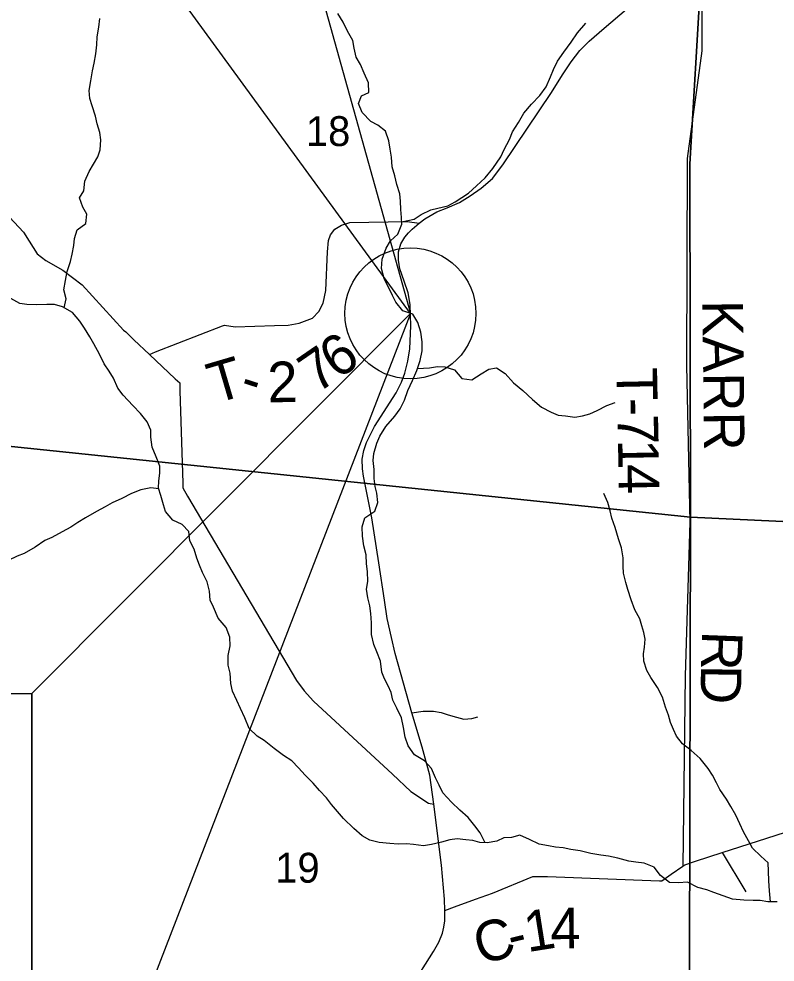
# Model space of a CAD drawing. Extents: x 0 to 34, y 0 to 22.
# Drawn here: x 26.174 to 27.233, y 16.193 to 17.514 of the extents above; entities that cross this region are included whole.
import ezdxf

# ---------------------------------------------------------------- set-up
doc = ezdxf.new("R2010")
doc.units = 0
for name, color, linetype in [('GM_X_Corporation', 7, 'Continuous'), ('GM_X_County_Road', 7, 'Continuous'), ('GM_X_County_Road_Text', 7, 'Continuous'), ('GM_X_Minor_River', 7, 'Continuous'), ('GM_X_Section_Text', 7, 'Continuous'), ('GM_X_State_Route', 7, 'Continuous'), ('GM_X_Township_Road', 7, 'Continuous'), ('GM_X_Township_Road_Text', 7, 'Continuous'), ('SH_Data', 7, 'Continuous')]:
    doc.layers.add(name, color=color, linetype=linetype)

msp = doc.modelspace()

# ---------------------------------------------------------------- linework, layer by layer
at = {"layer": 'GM_X_Corporation'}
for points in [[(26.3421, 17.8905), (26.9688, 17.8482), (27.1442, 17.8319), (27.1132, 17.3107), (27.1145, 16.8163), (26.06, 16.9257), (26.0658, 16.9791), (26.1183, 17.6235)], [(26.0314, 16.5691), (26.06, 16.9257), (27.1145, 16.8163), (27.112, 15.7689), (26.1924, 15.8415)]]:
    msp.add_lwpolyline(points, dxfattribs=at)
for points in [[(27.1442, 17.8319), (27.2101, 17.8272), (28.2146, 17.7472), (28.2741, 17.7417), (28.199, 16.7653), (27.1145, 16.8163), (27.1132, 17.3107)], [(27.1145, 16.8163), (28.199, 16.7653), (28.1104, 15.671), (27.112, 15.7689)]]:
    msp.add_lwpolyline(points, close=True, dxfattribs=at)
at = {"layer": 'GM_X_County_Road'}
msp.add_lwpolyline([(26.7705, 16.2651), (26.7841, 16.2703), (26.8132, 16.281), (26.8372, 16.2896), (26.8937, 16.313), (26.9141, 16.3129), (27.0708, 16.3069), (27.0742, 16.3068), (27.0874, 16.3161), (27.1034, 16.3274), (27.1064, 16.3295), (27.1215, 16.3344), (27.1588, 16.3464), (27.448, 16.4395), (27.452, 16.4408), (27.4615, 16.4528), (27.5592, 16.5754), (27.5725, 16.5898), (27.6861, 16.7116), (27.6929, 16.7189)], dxfattribs=at)
at = {"layer": 'GM_X_Minor_River'}
for points in [[(26.827, 16.3603), (26.82, 16.3743), (26.8125, 16.3838), (26.8031, 16.3956), (26.7914, 16.4059), (26.7797, 16.4169), (26.7676, 16.4302), (26.7624, 16.4408), (26.7571, 16.4511), (26.7519, 16.464), (26.7417, 16.475), (26.7281, 16.4834), (26.7191, 16.496), (26.715, 16.5081), (26.7127, 16.5218), (26.7098, 16.5351), (26.7034, 16.5487), (26.6978, 16.5597), (26.6951, 16.5704), (26.691, 16.5802), (26.6861, 16.5897), (26.6824, 16.5992), (26.6802, 16.6144), (26.6753, 16.6277), (26.6712, 16.6379), (26.6678, 16.652), (26.6679, 16.6683), (26.6668, 16.6815), (26.6653, 16.6922), (26.6627, 16.7032), (26.6609, 16.7153), (26.6624, 16.7259), (26.6621, 16.7399), (26.6606, 16.7506), (26.6603, 16.7634), (26.6569, 16.776), (26.6551, 16.7896), (26.6548, 16.8025), (26.6586, 16.8154), (26.6726, 16.8244), (26.6765, 16.8365), (26.6754, 16.8498), (26.6728, 16.8593), (26.6713, 16.8703), (26.6713, 16.8828), (26.6702, 16.8957), (26.671, 16.9052), (26.6753, 16.9199), (26.6795, 16.9298), (26.6878, 16.943), (26.7004, 16.9574), (26.708, 16.968), (26.7137, 16.9801), (26.7187, 16.9937), (26.7251, 17.0077), (26.7312, 17.0217), (26.7358, 17.0357), (26.7385, 17.049), (26.7386, 17.0615), (26.7367, 17.0751), (26.7326, 17.0888), (26.7255, 17.1006), (26.7115, 17.1052), (26.7017, 17.1173), (26.6972, 17.1268), (26.6856, 17.1504), (26.6815, 17.1644), (26.6826, 17.1773), (26.6884, 17.1928), (26.6945, 17.2034), (26.7047, 17.2125), (26.7101, 17.2265), (26.7097, 17.236), (26.709, 17.247), (26.7083, 17.2587), (26.7072, 17.269), (26.7031, 17.2819), (26.7005, 17.2944), (26.6967, 17.3069), (26.6956, 17.3202), (26.6938, 17.3316), (26.692, 17.3433), (26.6871, 17.3566), (26.6765, 17.365), (26.6667, 17.3703), (26.6546, 17.3829), (26.6494, 17.3954), (26.6536, 17.4064), (26.6642, 17.4109), (26.6635, 17.4245), (26.6575, 17.4378), (26.6522, 17.45), (26.6462, 17.4602), (26.6433, 17.4731), (26.6414, 17.4838), (26.6339, 17.4967), (26.6279, 17.5092), (26.6207, 17.5217)], [(26.2374, 17.1095), (26.2402, 17.1218), (26.2368, 17.1347), (26.2392, 17.1475), (26.2419, 17.16), (26.2464, 17.1744), (26.2488, 17.1843), (26.2511, 17.1968), (26.2519, 17.2066), (26.2557, 17.2184), (26.2678, 17.2274), (26.2694, 17.2403), (26.2637, 17.2502), (26.2589, 17.2635), (26.265, 17.2733), (26.2662, 17.2866), (26.2723, 17.3002), (26.2844, 17.3206), (26.2879, 17.3308), (26.2887, 17.3445), (26.2876, 17.3547), (26.2835, 17.3668), (26.2812, 17.3779), (26.2768, 17.3923), (26.2734, 17.4025), (26.2727, 17.4135), (26.275, 17.4272), (26.2773, 17.4412), (26.2796, 17.4518), (26.2819, 17.465), (26.2831, 17.4775), (26.2839, 17.4889), (26.2862, 17.5025), (26.2874, 17.5147)], [(26.7099, 17.2298), (26.7275, 17.2336), (26.7373, 17.24), (26.751, 17.2464), (26.7608, 17.249), (26.7745, 17.2524), (26.7847, 17.258), (26.7942, 17.2637), (26.8037, 17.2701), (26.8147, 17.2803), (26.8268, 17.2912), (26.8378, 17.3045), (26.8489, 17.3207), (26.8534, 17.3309), (26.8607, 17.3453), (26.8653, 17.3559), (26.8733, 17.3688), (26.8812, 17.382), (26.8915, 17.3945), (26.9033, 17.4069), (26.9124, 17.419), (26.9181, 17.433), (26.9227, 17.4429), (26.928, 17.455), (26.9372, 17.4675), (26.9474, 17.4814), (26.9562, 17.4943), (26.968, 17.5079)], [(26.4268, 16.7488), (26.4231, 16.7587), (26.4193, 16.7712), (26.4133, 16.783), (26.4119, 16.7959), (26.4025, 16.8058), (26.3896, 16.8119), (26.3791, 16.824), (26.3765, 16.8335), (26.3727, 16.8464), (26.3697, 16.857), (26.3701, 16.8669), (26.3713, 16.8779), (26.3714, 16.8874), (26.3665, 16.9007), (26.3605, 16.9143), (26.359, 16.9284), (26.3587, 16.9378), (26.3538, 16.9496), (26.3444, 16.9614), (26.3335, 16.9724), (26.3199, 16.9869), (26.3127, 16.9968), (26.3067, 17.0108), (26.3004, 17.0207), (26.2936, 17.031), (26.2868, 17.0446), (26.2789, 17.0591), (26.2733, 17.0689), (26.2658, 17.0811), (26.2594, 17.0906), (26.2492, 17.1028), (26.2352, 17.1108), (26.2239, 17.1142), (26.2133, 17.1139), (26.1982, 17.1136), (26.1853, 17.114), (26.1755, 17.1152), (26.163, 17.1224)], [(26.7322, 17.0246), (26.7487, 17.0254), (26.76, 17.0273), (26.7702, 17.0269), (26.7838, 17.0226), (26.7944, 17.0105), (26.8084, 17.0085), (26.8213, 17.0168), (26.8319, 17.0236), (26.8425, 17.0251), (26.8549, 17.0174), (26.8666, 17.0045), (26.8798, 16.9935), (26.893, 16.9809), (26.9058, 16.9702), (26.9194, 16.963), (26.9292, 16.9592), (26.9391, 16.958), (26.9523, 16.9564), (26.9633, 16.9579), (26.9735, 16.9609), (26.9837, 16.9654), (26.997, 16.9725), (27.0087, 16.9767)], [(26.37, 16.856), (26.3588, 16.8571), (26.3448, 16.8545), (26.3319, 16.8492), (26.3182, 16.8425), (26.3046, 16.8361), (26.2947, 16.8308), (26.2826, 16.824), (26.2674, 16.8154), (26.2568, 16.8086), (26.247, 16.8022), (26.2345, 16.7958), (26.2204, 16.7879), (26.2102, 16.7837), (26.1969, 16.7743), (26.1814, 16.7653), (26.1719, 16.7615), (26.159, 16.7555), (26.148, 16.7533), (26.1234, 16.7477), (26.1132, 16.7466), (26.1019, 16.747)], [(27.2263, 16.2776), (27.2249, 16.2928), (27.2238, 16.3068), (27.2235, 16.3204), (27.2228, 16.3322), (27.2126, 16.3413), (27.2013, 16.3527), (27.1953, 16.363), (27.1885, 16.3755), (27.1832, 16.3869), (27.1776, 16.3987), (27.1708, 16.4112), (27.1645, 16.4211), (27.1554, 16.4348), (27.1505, 16.4443), (27.1453, 16.4549), (27.1389, 16.4644), (27.128, 16.4781), (27.1151, 16.4895), (27.1031, 16.4987), (27.0948, 16.5093), (27.0903, 16.5188), (27.0865, 16.5287), (27.0835, 16.5389), (27.0794, 16.5503), (27.0753, 16.564), (27.0682, 16.5777), (27.0588, 16.5917), (27.0531, 16.6016), (27.049, 16.6145), (27.0483, 16.6247), (27.0499, 16.6342), (27.051, 16.6452), (27.0492, 16.6547), (27.0462, 16.6642), (27.0436, 16.674), (27.0364, 16.6862), (27.0312, 16.7002), (27.0267, 16.7147), (27.0237, 16.7249), (27.0204, 16.7378), (27.02, 16.7477), (27.0201, 16.7594), (27.0175, 16.7731), (27.0133, 16.786), (27.0089, 16.8019), (27.004, 16.8148), (27.0018, 16.8251), (26.9988, 16.8365), (26.9931, 16.8494)], [(27.2358, 16.2776), (27.2226, 16.2776), (27.2116, 16.2792), (27.2018, 16.2792), (27.1889, 16.2796), (27.173, 16.2812), (27.1598, 16.2858), (27.1469, 16.2904), (27.1371, 16.2942), (27.1246, 16.2977), (27.1103, 16.3049), (27.0974, 16.3042), (27.085, 16.3047), (27.0725, 16.3142), (27.0635, 16.326), (27.0495, 16.3317), (27.0378, 16.3329), (27.0279, 16.3345), (27.0128, 16.3387), (26.9996, 16.3414), (26.989, 16.3426), (26.9746, 16.3453), (26.9599, 16.3491), (26.947, 16.3507), (26.9361, 16.353), (26.9255, 16.3542), (26.9153, 16.3557), (26.9024, 16.3584), (26.8888, 16.3649), (26.8752, 16.3707), (26.8639, 16.3677), (26.8529, 16.367), (26.8431, 16.3625), (26.8298, 16.3602), (26.8196, 16.3606), (26.8098, 16.3633), (26.7996, 16.3645), (26.7878, 16.3657), (26.7776, 16.3642), (26.7655, 16.3609), (26.7515, 16.3579), (26.7405, 16.356), (26.7265, 16.3576), (26.7167, 16.3588), (26.705, 16.3584), (26.6936, 16.3592), (26.6785, 16.3604), (26.6653, 16.3639), (26.6547, 16.37), (26.643, 16.3803), (26.6287, 16.394), (26.62, 16.4042), (26.6117, 16.4138), (26.6046, 16.4233), (26.5948, 16.4335), (26.5861, 16.4438), (26.5748, 16.4548), (26.5654, 16.4651), (26.556, 16.475), (26.5443, 16.4822), (26.5314, 16.4921), (26.5175, 16.5032), (26.5077, 16.5093), (26.4964, 16.5203), (26.4904, 16.5351), (26.4844, 16.5484), (26.4791, 16.5594), (26.4731, 16.5727), (26.4709, 16.5834), (26.4698, 16.5978), (26.4672, 16.6091), (26.4672, 16.6224), (26.4699, 16.6361), (26.4692, 16.6482), (26.4643, 16.6618), (26.453, 16.6748), (26.4463, 16.69), (26.4418, 16.6998), (26.4407, 16.7127), (26.4377, 16.7256), (26.431, 16.7389), (26.4268, 16.7488)]]:
    msp.add_lwpolyline(points, dxfattribs=at)
at = {"layer": 'GM_X_State_Route'}
msp.add_lwpolyline([(26.692, 16.109), (26.7547, 16.208), (26.7622, 16.2211), (26.7672, 16.2337), (26.7692, 16.2418), (26.7704, 16.2509), (26.7705, 16.2651), (26.7697, 16.2812), (26.7657, 16.329), (26.755, 16.4142), (26.7494, 16.4549), (26.7385, 16.4939), (26.7243, 16.5421), (26.7007, 16.6252), (26.6957, 16.6475), (26.6896, 16.6741), (26.686, 16.6998), (26.6781, 16.7524), (26.6684, 16.8152), (26.6566, 16.8737), (26.6551, 16.8837), (26.6547, 16.8975), (26.6569, 16.9094), (26.6607, 16.9206), (26.6643, 16.9283), (26.6717, 16.9431), (26.7023, 16.9904), (26.7097, 17.0052), (26.7143, 17.0179), (26.7185, 17.0347), (26.7213, 17.0518), (26.723, 17.084), (26.7218, 17.1139), (26.7189, 17.1303), (26.7136, 17.1468), (26.7075, 17.1639), (26.7055, 17.1762), (26.7057, 17.1876), (26.709, 17.1991), (26.7146, 17.2081), (26.7195, 17.2145), (26.7246, 17.2193), (26.7343, 17.228), (26.7422, 17.2339), (26.7593, 17.2438), (26.7735, 17.2495), (26.7908, 17.2568), (26.8059, 17.266), (26.8212, 17.2768), (26.8373, 17.2903), (26.8518, 17.3097), (26.9195, 17.4111), (26.9351, 17.4355), (26.9473, 17.4539), (26.9593, 17.4695), (26.9725, 17.483), (26.9933, 17.5012), (27.0652, 17.5627)], dxfattribs=at)
at = {"layer": 'GM_X_Township_Road'}
msp.add_line((27.1588, 16.3464), (27.1918, 16.2915), dxfattribs=at)
for points in [[(27.1295, 17.6076), (27.1302, 17.4692), (27.1094, 17.3183), (27.1089, 17.0285), (27.1135, 16.8092), (27.107, 16.5939), (27.1034, 16.3274)], [(26.1609, 17.2361), (26.1805, 17.2153), (26.1884, 17.2028), (26.1995, 17.185), (26.2119, 17.1757), (26.2358, 17.162), (26.2629, 17.1416), (26.3205, 17.0781), (26.3238, 17.0756), (26.3352, 17.0647), (26.3569, 17.0442), (26.393, 17.0101), (26.3993, 17.0042), (26.3996, 16.9929), (26.4037, 16.8637), (26.4038, 16.8572), (26.4102, 16.8454), (26.5628, 16.5873), (26.5734, 16.573), (26.5867, 16.5584), (26.697, 16.4561), (26.723, 16.432), (26.7473, 16.4155), (26.755, 16.4142)], [(26.3569, 17.0442), (26.3654, 17.0476), (26.4591, 17.084), (26.4619, 17.0851), (26.477, 17.0827), (26.5321, 17.0846), (26.551, 17.0851), (26.5666, 17.0878), (26.5849, 17.0948), (26.5942, 17.1042), (26.6, 17.116), (26.6038, 17.1338), (26.6061, 17.188), (26.6074, 17.2038), (26.6102, 17.2117), (26.6164, 17.2193), (26.6256, 17.2252), (26.6376, 17.2288), (26.7175, 17.2301), (26.7343, 17.228)], [(26.7243, 16.5421), (26.7399, 16.5444), (26.7545, 16.5447), (26.7652, 16.5424), (26.7749, 16.5395), (26.7866, 16.536), (26.797, 16.5334), (26.8083, 16.5344), (26.8167, 16.5367)]]:
    msp.add_lwpolyline(points, dxfattribs=at)
at = {"layer": 'SH_Data'}
for points in [[(26.3421, 18.4635), (26.7223, 17.1016), (26.3421, 17.6235)], [(26.1924, 16.5691), (26.7223, 17.1016), (26.1924, 15.7291)], [(24.3169, 16.5691), (26.1924, 16.5691), (26.1924, 15.7291), (24.3169, 15.7291)]]:
    msp.add_lwpolyline(points, close=True, dxfattribs=at)
msp.add_circle((26.7223, 17.1016), 0.0917, dxfattribs=at)

# ---------------------------------------------------------------- texts
at = {"layer": 'GM_X_County_Road_Text'}
for s, rotation, p in [('1', 9.0243, (26.886, 16.2069)), ('4', 0.51, (26.9184, 16.2122)), ('C', 16.1572, (26.8204, 16.1887)), ('-', 13.9208, (26.8646, 16.2015))]:
    msp.add_text(s, height=0.0568, rotation=rotation, dxfattribs=at).set_placement(p)
at = {"layer": 'GM_X_Section_Text'}
for s, p in [('18', (26.5758, 17.3359)), ('19', (26.5329, 16.3043))]:
    msp.add_text(s, height=0.04186, rotation=0, dxfattribs=at).set_placement(p)
at = {"layer": 'GM_X_Township_Road_Text'}
for s, height, rotation, p in [('KARR', 0.05682, 270.7324, (27.1308, 17.1199)), ('6', 0.0568, 34.0518, (26.6197, 17.0081)), ('7', 0.0568, 34.612, (26.5912, 16.9884)), ('T', 0.0568, 16.4327, (26.4485, 16.9747)), ('2', 0.0568, 1.1983, (26.5226, 16.9768)), ('T', 0.0568, 271.1851, (27.0106, 17.0252)), ('-', 0.0568, 342.1953, (26.4804, 16.9868)), ('-', 0.0568, 271.1841, (27.0115, 16.9827)), ('7', 0.0568, 271.1678, (27.012, 16.9596)), ('1', 0.0568, 271.0424, (27.0127, 16.9249)), ('4', 0.0568, 270.8163, (27.0133, 16.8903)), ('R', 0.0568, 267.8685, (27.1308, 16.6575)), ('D', 0.0568, 269.1867, (27.129, 16.6095))]:
    msp.add_text(s, height=height, rotation=rotation, dxfattribs=at).set_placement(p)

doc.saveas('drawing.dxf')
